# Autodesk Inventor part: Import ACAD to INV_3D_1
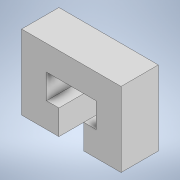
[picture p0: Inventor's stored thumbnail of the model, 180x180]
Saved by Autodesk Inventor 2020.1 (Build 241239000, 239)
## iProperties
Created: 2019-11
Part Number: Import ACAD to INV_3D_1
Material: Generic
Document SubType Name: Modeling
Designer: Synergysoft Dell02
Density: 1 g/cm^3
Appearance: Default
Author: Synergysoft Dell02
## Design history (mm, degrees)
sketch "Sketch1"
  geometry: L1 (0, 0)-(30, 0); L2 (30, 0)-(30, 20); L3 (30, 20)-(20, 20); L4 (20, 20)-(20, 40); L5 (20, 40)-(60, 40); L6 (60, 40)-(60, 20); L7 (60, 20)-(50, 20); L8 (50, 20)-(50, 0); L9 (50, 0)-(80, 0); L10 (80, 0)-(80, 60); L11 (80, 60)-(0, 60); L12 (0, 60)-(0, 0); L13 (133.795, 0)-(163.795, 0); L14 (163.795, 0)-(163.795, 60); L15 (163.795, 60)-(133.795, 60); L16 (133.795, 60)-(133.795, 0); L17 (133.795, 40)-(163.795, 40); L18 (133.795, 20)-(163.795, 20); L19 (0, -50)-(80, -50); L20 (80, -50)-(80, -80); L21 (80, -80)-(0, -80); L22 (0, -80)-(0, -50); L23 (30, -50)-(30, -80); L24 (50, -50)-(50, -80); 1 further point
  constraints: 48 end point, 13 parallel, 8 perpendicular, 8 point on line, 3 collinear, 1 coincident
  dimensions: "d1" = 60 distance of L11.end L1.start; "d3" = 40 distance of L4.end L5.end; "d5" = 30 distance of L1.start L1.end; "d7" = 80 distance of L1.start L9.end; "d9" = 20 distance of L1.end L8.end; "d13" = 20 distance of L3.end L4.end; "d15" = 30 distance of L13.start L13.end
extrude "Extrusion1" new body sketch "Sketch1" distance "d16" = 30 (= d15); taper "d17" = 0 deg
body "Solid1"
